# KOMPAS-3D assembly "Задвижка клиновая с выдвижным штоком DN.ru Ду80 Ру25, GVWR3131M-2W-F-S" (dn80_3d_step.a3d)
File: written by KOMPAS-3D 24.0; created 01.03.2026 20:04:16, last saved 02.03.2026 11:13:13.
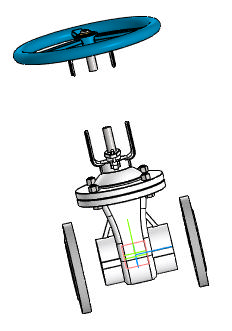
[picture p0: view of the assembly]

Document properties: Автор: R2D2; Полное имя файла: E:\Работа\Зайцев\GVWR3131M-2W-F-S Задвижка клиновая 30нж64нж DN.ru  Ду50-150 Ру25\исходные данные\DN80\dn80_3d_step.a3d

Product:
- Component [detail]: Деталь2  | qty 1  | pos. 1  | Масса: 4.922929; Автор: R2D2; additional columns: Типовые; source file: Деталь2 Деталь2.m3d
- Component [detail]: AS 1110 - M12 x 45  | qty 4  | pos. 2  | Масса: 0.056439; Комментарий: Болты и винты   шестигранные точные   метрические ISO; Автор: R2D2; additional columns: Сталь, мягкая; source file: AS 1110 - M12 x 45 AS 1110 - M12 x 45.m3d
- Component [detail]: ANSI B18.2.4.2M - M12x1,75 - 18  | designation ANSI B18.2.4.2M - M12x1,75  | qty 4  | pos. 3  | Масса: 0.018772; Комментарий: Типы метрических   шестигранных гаек   2; Автор: R2D2; additional columns: Сталь, мягкая; source file: ANSI B18.2.4.2M - M12x1,75 ANSI B18.2.4.2M - M12x1,75 - 18.m3d
- Component [detail]: ANSI B18.2.4.2M - M5x0,8 - 8  | designation ANSI B18.2.4.2M - M5x0,8  | qty 2  | pos. 4  | Масса: 0.00167; Комментарий: Типы метрических   шестигранных гаек   2; Автор: R2D2; additional columns: Сталь, мягкая; source file: ANSI B18.2.4.2M - M5x0,8 ANSI B18.2.4.2M - M5x0,8 - 8.m3d
- Component [detail]: Деталь1  | qty 1  | pos. 5  | Масса: 23.507576; additional columns: Типовые; source file: 2.m3d
- Component [detail]: Деталь1  | qty 1  | pos. 5  | Масса: 0.546953; Автор: R2D2; additional columns: Типовые; source file: 3.m3d
- Component [detail]: Деталь1  | qty 2  | pos. 5  | Масса: 3.627543; Автор: R2D2; additional columns: Типовые; source file: 1.m3d
- Part/product: Задвижка клиновая с выдвижным штоком DN.ru Ду80 Ру25  | designation GVWR3131M-2W-F-S
    Масса: 25.5
    Раздел спецификации: Прочие изделия
    Примечание: D040-09368

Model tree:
1. Массив по концентрической сетке:1  (labels: Грань.Твердое тело1)  (4 pattern instances)
     Шаг 2 = 360
2. Массив по концентрической сетке:2  (with: Грань.Элемент вращения:1)  (labels: Грань.Твердое тело1; Грань.Solid1)  (2 pattern instances)
     Шаг 2 = 360; Расстояние = -495; Расстояние = -140; Ориентация = 2

Referenced files in E:\Работа\Зайцев\GVWR3131M-2W-F-S Задвижка клиновая 30нж64нж DN.ru  Ду50-150 Ру25\исходные данные\DN80\: Деталь2 Деталь2.m3d, AS 1110 - M12 x 45 AS 1110 - M12 x 45.m3d, ANSI B18.2.4.2M - M12x1,75 ANSI B18.2.4.2M - M12x1,75 - 18.m3d, ANSI B18.2.4.2M - M5x0,8 ANSI B18.2.4.2M - M5x0,8 - 8.m3d, 2.m3d, 1.m3d, 3.m3d
Referenced files in E:\Работа\Зайцев\GVWR3131M-2W-F-S Задвижка клиновая с выдвижным штоком DN.ru Ду50-200 Ру63\DN80\исходные материалы\: 1.m3d, ANSI B18.2.4.2M - M12x1,75 ANSI B18.2.4.2M - M12x1,75 - 18.m3d, AS 1110 - M12 x 45 AS 1110 - M12 x 45.m3d, ANSI B18.2.4.2M - M5x0,8 ANSI B18.2.4.2M - M5x0,8 - 8.m3d
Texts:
  Программные изделия  и базы данных
  ANSI B18.2.4.2M - M12x1,75
  ANSI B18.2.4.2M - M5x0,8
  GVWR3131M-2W-F-S
  Деталь2 Деталь2
  AS 1110 - M12 x 45 AS 1110 - M12 x 45 (1)
  ANSI B18.2.4.2M - M12x1,75 ANSI B18.2.4.2M - M12x1,75 - 18 (1)
  ANSI B18.2.4.2M - M5x0,8 ANSI B18.2.4.2M - M5x0,8 - 8 (1)
  Деталь1 Деталь1
  Деталь1 Деталь1 (1)
  Деталь1 Деталь1 (2)
  ANSI B18.2.4.2M - M12x1,75 ANSI B18.2.4.2M - M12x1,75 - 18 (2)
  AS 1110 - M12 x 45 AS 1110 - M12 x 45 (2)
  ANSI B18.2.4.2M - M12x1,75 ANSI B18.2.4.2M - M12x1,75 - 18 (3)
  AS 1110 - M12 x 45 AS 1110 - M12 x 45 (3)
  ANSI B18.2.4.2M - M12x1,75 ANSI B18.2.4.2M - M12x1,75 - 18 (4)
  AS 1110 - M12 x 45 AS 1110 - M12 x 45 (4)
  ANSI B18.2.4.2M - M5x0,8 ANSI B18.2.4.2M - M5x0,8 - 8 (2)
  Ось Y.Начало координат
  Ось Z.Начало координат
  Плоскость ZX.Начало координат
  Плоскость XY.Начало координат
